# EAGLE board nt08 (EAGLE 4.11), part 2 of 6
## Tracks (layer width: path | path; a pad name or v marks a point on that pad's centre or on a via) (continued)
CK00\  (via drill 0.61) (continued)
  Top 0.254: v323.21,270.51 325.12,268.61 325.12,267.97 IC77.6 | v19.68,473.71 19.05,473.07 19.05,443.87 22.23,440.69 22.23,309.25 v21.59,308.61 | v258.44,307.34 266.7,299.08 v266.7,290.19 | v288.29,286.38 290.19,284.48 v290.19,274.95
  Bottom 0.254: 316.23,269.88 316.23,271.78 317.5,273.05 IC77.12 | 316.23,269.88 322.58,269.88 v323.21,270.51 | v19.68,473.71 -5.71,473.71 -6.99,474.98 M916_3.N2 | v21.59,308.61 22.86,307.34 60.33,307.34 60.96,306.7 104.78,306.7 105.41,307.34 v258.44,307.34 | v266.7,290.19 271.14,285.75 287.65,285.75 v288.29,286.38 | v290.19,274.95 295.27,269.88 316.23,269.88
CK01  (via drill 0.61)
  Top 0.254: IC119.12 517.52,384.18 516.25,384.18 IC119.13 515.62,383.54 514.35,382.27 514.35,340.36 v514.99,339.73 | v317.5,271.14 317.5,270.51 314.96,267.97 IC77.2 | v327.66,334.01 325.75,332.11 325.75,274.95 IC77.9
  Bottom 0.254: IC119.10 522.61,384.18 521.34,382.9 520.07,382.9 518.79,384.18 IC119.12 | v317.5,271.14 318.77,272.42 323.21,272.42 324.49,273.69 IC77.9 | v514.99,339.73 429.26,339.73 423.55,334.01 v327.66,334.01
CK01\  (via drill 0.61)
  Top 0.254: v520.7,268.61 521.97,269.88 521.97,450.85 520.7,452.12 IC121.4 521.34,452.75 522.61,452.75 IC121.5
  Bottom 0.254: v520.7,268.61 471.81,268.61 469.26,271.14 415.29,271.14 412.12,274.32 365.12,274.32 364.49,273.69 328.3,273.69 IC77.8 | IC121.2 516.25,452.75 517.52,451.49 518.79,451.49 520.07,452.75 IC121.4
CLR_DF\  (via drill 0.61)
  Top 0.254: v170.18,464.19 171.45,462.92 v171.45,417.19 | v596.26,427.99 599.44,424.81 599.44,417.83 600.71,416.56 IC137.4
  Bottom 0.254: v170.18,464.19 158.12,464.19 140.97,481.33 50.8,481.33 50.16,480.69 IC15.8 | v171.45,417.19 172.09,417.83 365.12,417.83 375.29,427.99 v596.26,427.99
CLR_DTF\  (via drill 0.61)
  Top 0.254: v567.69,12.7 582.29,27.3 582.29,371.48 589.91,379.1 v589.91,452.75
  Bottom 0.254: v567.69,12.7 523.24,12.7 521.34,14.61 IC112.4 | v589.91,452.75 592.46,455.3 598.8,455.3 600.08,454.02 IC138.4
COMP+SH  (via drill 0.61)
  Top 0.254: v516.89,19.05 516.89,69.85 | 516.89,69.85 518.16,71.12 IC113.3 | 518.16,81.92 516.89,81.92 516.89,69.85 | 518.16,81.92 518.79,81.92 520.07,80.64 IC113.11 | 518.16,81.92 518.16,109.22 IC114.3 518.16,111.76 519.43,113.03 519.43,157.48 518.16,158.75 518.16,176.53 519.43,177.8 519.43,208.28 520.7,209.55 IC116.11
  Bottom 0.254: v516.89,19.05 516.25,19.68 72.39,19.68 72.39,16.51 IC16.1
CSTA  (via drill 0.61)
  Top 0.254: v114.94,516.25 98.42,499.75 v98.42,396.24
  Bottom 0.254: v114.94,516.25 240.66,516.25 241.94,517.52 IC55.10 | v98.42,396.24 93.34,391.16 -2.54,391.16 -3.81,389.89 M916_22.P2
CSTA\  (via drill 0.61)
  Top 0.254: v45.72,236.85 45.72,195.58 IC12.9 | v241.3,425.45 241.3,511.81 240.66,512.45 240.66,516.25 240.03,516.89 IC55.11 | v222.25,419.74 220.98,418.46 220.98,311.15 221.62,310.51 221.62,264.16 219.71,262.25 v219.71,238.76
  Bottom 0.254: v45.72,236.85 82.55,236.85 83.82,238.12 219.71,238.12 | 219.71,238.12 224.79,238.12 226.06,239.4 351.79,239.4 360.68,248.28 404.5,248.28 407.04,250.82 IC87.8 | v241.3,425.45 235.59,419.74 v222.25,419.74 | v219.71,238.76 219.71,238.12
DATA
  Bottom 0.254: IC99.11 440.06,441.32 438.79,440.06 324.49,440.06 323.85,440.69 320.04,436.88 191.13,436.88 189.87,435.61 77.47,435.61 73.03,440.06 71.12,440.06 M916_10.M1
DATA\  (via drill 0.61)
  Top 0.254: v467.36,438.15 471.17,434.34 v471.17,421 467.36,417.19 467.36,191.77 469.26,189.87 v469.26,186.06 | v333.38,38.1 341.63,46.35 341.63,184.15 v341,184.78
  Bottom 0.254: v467.36,438.15 445.77,438.15 443.23,440.69 IC99.10 | v471.17,421 476.25,415.93 512.45,415.93 IC120.1 | v333.38,38.1 325.12,38.1 323.85,36.83 317.5,36.83 315.6,34.92 IC71.2 | v341,184.78 342.26,186.06 v469.26,186.06 471.81,186.06 IC107.1
DB_00\
  Top 0.254: SV10.D -25.4,192.41 -26.67,191.13 -26.67,178.44 -25.4,177.16 SV5.D
  Bottom 0.254: IC24.3 160.66,168.28 156.84,172.09 118.75,172.09 118.11,172.72 22.23,172.72 21.59,172.09 -22.86,172.09 -24.13,173.35 -24.13,175.9 -25.4,175.9 SV5.D
DB_00\_  (via drill 0.61)
  Top 0.254: IC24.1 156.84,167 158.12,167 IC24.2 | v118.11,171.45 118.11,212.09 114.94,215.26 114.94,231.78 115.57,232.41 114.3,233.68 114.3,294.64 116.2,296.55 116.2,341 114.94,342.26 114.94,371.48 116.2,372.75 116.2,434.34 117.47,435.61 117.47,491.49 116.84,492.12 116.84,543.56 113.03,547.37 IC21.1
  Bottom 0.254: v118.11,171.45 121.28,168.28 155.57,168.28 IC24.1
DB_01\  (via drill 0.61)
  Top 0.254: v163.83,172.09 163.83,173.99 IC24.5
  Bottom 0.254: v163.83,172.09 163.19,172.72 119.38,172.72 118.75,173.35 21.59,173.35 20.95,172.72 -18.41,172.72 -19.05,173.35 -19.05,175.9 -20.32,175.9 SV5.J -20.32,177.16 -21.59,177.16 -21.59,191.13 -20.32,192.41 SV10.J
DB_01\_  (via drill 0.61)
  Top 0.254: IC24.7 159.38,174.62 160.66,174.62 IC24.6 | v120.02,426.72 120.02,546.74 120.65,547.37 IC21.4 | v126.36,420.37 139.06,407.67 139.06,287.65 138.43,287.02 138.43,269.88 137.16,268.61 v137.16,177.8
  Bottom 0.254: v126.36,420.37 v120.02,426.72 | v137.16,177.8 137.79,177.16 156.84,177.16 158.12,175.9 IC24.7
DB_02\  (via drill 0.61)
  Top 0.254: v158.75,201.93 161.29,204.47 IC25.3
  Bottom 0.254: v158.75,201.93 157.48,200.66 135.89,200.66 134.62,199.39 57.78,199.39 57.15,200.03 -16.51,200.03 -17.78,201.29 -19.05,201.29 -21.59,198.75 -21.59,194.31 -17.14,194.31 -15.88,193.04 SV10.N -15.24,192.41 -13.97,192.41 -13.97,189.87 -14.61,189.23 -15.24,189.23 -15.24,177.16 SV5.N
DB_02\_  (via drill 0.61)
  Top 0.254: v139.7,207.01 139.7,220.98 138.43,222.25 138.43,268.61 139.06,269.24 139.06,286.38 139.7,287.02 139.7,359.41 146.05,365.76 146.05,445.77 124.46,467.36 124.46,553.72 123.19,554.99 IC21.10
  Bottom 0.254: IC25.2 158.12,205.1 156.84,205.1 IC25.1 156.21,207.01 v139.7,207.01
DB_03\  (via drill 0.61)
  Top 0.254: v134.62,210.19 133.99,209.55 v133.99,202.56 | v-9.53,202.56 -9.53,193.04 SV10.T
  Bottom 0.254: v134.62,210.19 160.66,210.19 163.19,212.72 IC25.5 | v133.99,202.56 v-9.53,202.56 | SV5.T -10.16,177.16 -10.16,189.23 -9.53,189.23 -8.89,189.87 -8.89,192.41 -10.16,192.41 SV10.T
DB_03\_  (via drill 0.61)
  Top 0.254: v148.59,298.45 148.59,361.95 149.86,363.22 149.86,558.16 117.47,558.16 116.2,556.89 IC21.13 | v158.75,292.1 160.02,290.83 160.02,215.9 158.75,214.63 IC25.7
  Bottom 0.254: IC25.7 159.38,212.72 160.66,212.72 IC25.6 | v148.59,298.45 154.94,292.1 v158.75,292.1
DB_04\  (via drill 0.61)
  Top 0.254: v160.02,207.65 160.02,214.63 160.66,215.26 160.66,241.94 161.29,242.57 IC26.3 | v-5.08,206.38 -5.08,193.68 SV10.X
  Bottom 0.254: v160.02,207.65 159.38,208.28 133.99,208.28 131.44,205.74 5.71,205.74 5.08,206.38 v-5.08,206.38 | SV5.X -5.71,176.53 -7.62,178.44 -7.62,189.23 -6.99,189.23 -6.35,189.87 -6.35,193.04 -5.71,193.04 SV10.X
DB_04\_  (via drill 0.61)
  Top 0.254: v148.59,241.94 142.88,236.22 142.88,181.61 149.22,175.26 149.22,19.68 152.4,16.51 IC22.1
  Bottom 0.254: v148.59,241.94 149.86,243.21 155.57,243.21 IC26.1 156.84,243.21 158.12,243.21 IC26.2
DB_05\  (via drill 0.61)
  Top 0.254: v165.1,203.84 165.1,248.92 163.83,250.19 IC26.5 | v0,203.84 0,193.68 SV10.BB | v0,188.59 0,177.16 SV5.BB
  Bottom 0.254: v165.1,203.84 v0,203.84 | v0,188.59 1.27,189.87 1.27,192.41 0,192.41 SV10.BB
DB_05\_  (via drill 0.61)
  Top 0.254: v166.37,243.84 166.37,13.34 161.93,13.34 160.66,14.61 IC22.4 | v162.56,246.38 161.29,247.65 161.29,250.19 IC26.6
  Bottom 0.254: v166.37,243.84 163.83,246.38 v162.56,246.38 | IC26.7 159.38,250.82 160.66,250.82 IC26.6
DB_06\  (via drill 0.61)
  Top 0.254: v149.22,276.23 149.86,275.59 149.86,227.97 144.15,222.25 v144.15,205.74 | v5.08,205.1 5.08,193.68 SV10.FF | v5.08,188.59 5.08,177.16 SV5.FF
  Bottom 0.254: v149.22,276.23 155.57,276.23 160.66,281.31 IC27.3 | v144.15,205.74 143.51,205.1 v5.08,205.1 | v5.08,188.59 6.35,189.87 6.35,192.41 5.08,192.41 SV10.FF
DB_06\_  (via drill 0.61)
  Top 0.254: v163.83,106.68 163.83,90.17 164.47,89.53 164.47,26.04 162.56,24.13 IC22.10 | v140.97,114.94 141.6,115.57 141.6,248.92 140.97,249.56 140.97,254 147.96,260.99 v147.96,280.04
  Bottom 0.254: IC27.2 158.12,281.31 156.84,281.31 IC27.1 155.57,281.31 149.22,281.31 v147.96,280.04 | v163.83,106.68 155.57,114.94 v140.97,114.94
DB_07\  (via drill 0.61)
  Top 0.254: v165.1,257.18 165.1,287.02 163.83,288.29 IC27.5 | v13.97,257.81 10.16,254 10.16,193.68 SV10.LL | v10.16,188.59 10.16,177.16 SV5.LL
  Bottom 0.254: v165.1,257.18 164.47,257.81 v13.97,257.81 | v10.16,188.59 11.43,189.87 11.43,192.41 10.16,192.41 SV10.LL
DB_07\_  (via drill 0.61)
  Top 0.254: v176.53,287.65 174.62,285.75 174.62,198.75 172.09,196.22 172.09,100.97 171.45,100.33 171.45,12.7 157.48,12.7 156.21,13.97 156.21,20.32 154.94,21.59 IC22.13
  Bottom 0.254: v176.53,287.65 163.19,287.65 161.93,288.93 IC27.6 160.66,288.93 159.38,288.93 IC27.7
DB_08\  (via drill 0.61)
  Top 0.254: v158.75,304.8 158.75,316.23 161.29,318.77 IC28.3 | v14.61,303.53 14.61,267.33 15.24,266.7 15.24,197.49 | 15.24,197.49 15.24,193.68 SV10.RR | 15.24,197.49 19.05,193.68 19.05,189.87 16.51,187.32 16.51,178.44 15.24,177.16 SV5.RR
  Bottom 0.254: v158.75,304.8 158.12,304.17 15.24,304.17 v14.61,303.53
DB_08\_  (via drill 0.61)
  Top 0.254: v150.5,223.52 150.5,94.61 152.4,92.71 IC23.1 | v156.21,227.97 157.48,229.24 157.48,317.5 156.21,318.77 IC28.1 156.84,319.4 158.12,319.4 IC28.2
  Bottom 0.254: v150.5,223.52 154.94,227.97 v156.21,227.97
DB_09\  (via drill 0.61)
  Top 0.254: v153.67,199.39 v153.67,325.75 | v-20.32,198.75 -22.86,196.22 -22.86,193.68 SV10.F
  Bottom 0.254: v153.67,325.75 161.93,325.75 163.19,327.02 IC28.5 | v153.67,199.39 152.4,198.12 56.52,198.12 55.88,198.75 v-20.32,198.75 | SV5.F -22.86,177.16 -22.86,189.23 -23.5,189.23 -24.13,189.87 -24.13,193.04 -23.5,193.04 SV10.F
DB_09\_  (via drill 0.61)
  Top 0.254: v167.64,93.98 168.91,95.25 168.91,152.4 167,154.31 167,243.21 167.64,243.84 167.64,272.42 165.74,274.32 165.74,299.08 165.1,299.72 v165.1,325.75 | IC28.7 159.38,327.02 160.66,327.02 IC28.6
  Bottom 0.254: v167.64,93.98 162.56,93.98 160.66,92.08 IC23.4 | v165.1,325.75 165.1,329.56 163.19,329.56 161.93,328.3 IC28.6
DB_10\  (via drill 0.61)
  Top 0.254: v149.86,356.24 150.5,355.6 150.5,227.33 145.41,222.25 v145.41,199.39 | v-17.78,200.03 -17.78,193.68 SV10.L
  Bottom 0.254: v149.86,356.24 159.38,356.24 160.66,357.5 IC29.3 | v145.41,199.39 144.78,198.75 57.15,198.75 56.52,199.39 -17.14,199.39 v-17.78,200.03 | SV5.L -17.78,177.16 -17.78,189.23 -17.14,189.23 -16.51,189.87 -16.51,192.41 -17.78,192.41 SV10.L
DB_10\_  (via drill 0.61)
  Top 0.254: v155.57,149.86 155.57,107.31 162.56,100.33 IC23.10 | v132.72,156.84 132.72,207.01 133.35,207.65 133.35,280.04 135.89,282.57 135.89,356.24 v135.25,356.87
  Bottom 0.254: IC29.2 158.12,357.5 156.84,357.5 IC29.1 155.57,358.14 136.53,358.14 v135.25,356.87 | v155.57,149.86 148.59,156.84 v132.72,156.84
DB_11\  (via drill 0.61)
  Top 0.254: v154.94,201.93 154.31,202.56 154.31,321.94 154.94,322.58 154.94,367.67 156.84,367.67 157.48,367.03 157.48,364.49 158.12,363.86 158.12,362.58 162.56,362.58 163.83,363.86 163.83,364.49 IC29.5 | v-10.79,201.29 -12.7,199.39 -12.7,193.68 SV10.R
  Bottom 0.254: v154.94,201.93 154.31,201.29 135.25,201.29 133.99,200.03 58.42,200.03 57.15,201.29 v-10.79,201.29 | SV5.R -12.7,177.16 -12.7,189.23 -12.06,189.23 -11.43,189.87 -11.43,192.41 -12.7,192.41 SV10.R
DB_11\_  (via drill 0.61)
  Top 0.254: v172.72,96.52 172.72,193.04 175.26,195.58 175.26,285.12 177.8,287.65 177.8,353.06 v174.62,356.24
  Bottom 0.254: v172.72,96.52 157.48,96.52 155.57,98.42 IC23.13 | v174.62,356.24 172.72,358.14 166.37,358.14 160.66,363.86 | 160.66,363.86 159.38,365.12 IC29.7 | 160.66,363.86 161.29,364.49 IC29.6
DF  (via drill 0.61)
  Top 0.254: v30.48,265.43 31.11,266.06 v31.11,411.48 31.11,431.17 v33.02,433.07 | v600.71,417.83 601.98,416.56 v601.98,411.48
  Bottom 0.254: v30.48,265.43 33.02,262.89 IC13.1 | v33.02,433.07 35.56,435.61 43.18,435.61 45.72,438.15 46.99,438.15 48.9,440.06 50.8,440.06 M916_10.E1 | v600.71,417.83 603.25,417.83 605.15,415.93 IC137.6 | v601.98,411.48 601.35,410.85 539.75,410.85 533.4,417.19 517.52,417.19 516.89,416.56 516.89,413.38 451.49,413.38 445.13,419.74 412.12,419.74 403.86,411.48 56.52,411.48 55.88,412.12 42.55,412.12 41.91,411.48 v31.11,411.48
DF\  (via drill 0.61)
  Top 0.254: v228.6,13.34 227.97,13.97 227.97,123.83 227.33,124.46 227.33,182.25 228.6,183.51 228.6,263.52 v227.33,264.8 | v180.34,266.06 180.97,266.7 180.97,318.13 185.42,322.58 185.42,368.3 184.78,368.94 184.78,416.56 | 184.78,416.56 184.78,542.92 192.41,550.54 195.58,550.54 195.58,549.91 IC45.2 | v596.9,429.26 601.98,424.18 601.98,417.83 603.25,416.56 IC137.5 | v520.07,429.26 v517.52,426.72 | v184.15,416.56 184.78,416.56
  Bottom 0.254: v228.6,13.34 234.31,7.62 313.69,7.62 316.87,4.45 IC70.12 | v227.33,264.8 181.61,264.8 v180.34,266.06 | v596.9,429.26 v520.07,429.26 | v517.52,426.72 516.89,427.36 375.92,427.36 365.12,416.56 v184.15,416.56
DTB_00  (via drill 0.61)
  Top 0.254: 444.5,455.93 447.04,458.47 v447.04,476.88 | 444.5,455.93 443.23,454.66 IC100.5 | v430.53,486.41 431.17,487.05 431.17,586.11 432.44,587.38 436.88,587.38 436.88,580.39 438.15,579.12 IC103.3 | v502.29,164.47 502.92,165.1 502.92,237.49 498.48,241.94 v498.48,432.44 | v447.04,436.88 444.5,439.42 444.5,455.93 | v83.19,415.29 76.83,408.94 76.83,365.12 77.47,364.49 M916_9.A2 | v375.92,438.79 v375.92,426.08
  Bottom 0.254: v447.04,476.88 437.51,486.41 v430.53,486.41 | v502.29,164.47 522.61,164.47 527.68,159.38 542.29,159.38 543.56,160.66 591.18,160.66 592.46,159.38 IC129.1 | v498.48,432.44 494.03,436.88 v447.04,436.88 445.77,436.88 443.23,439.42 376.56,439.42 v375.92,438.79 | v83.19,415.29 365.12,415.29 v375.92,426.08
DTB_00\  (via drill 0.61)
  Top 0.254: v427.36,457.2 427.99,457.83 427.99,531.5 363.22,596.26 114.3,596.26 114.3,551.18 115.57,549.91 IC21.2
  Bottom 0.254: v427.36,457.2 445.77,457.2 445.77,454.66 IC100.6
DTB_01  (via drill 0.61)
  Top 0.254: v488.95,167.64 488.95,121.92 486.41,119.38 486.41,62.23 477.52,53.34 IC105.12 | v486.41,454.66 498.48,442.6 498.48,437.51 497.2,436.25 497.2,196.85 501.65,192.41 v501.65,173.99 | v104.14,384.18 111.12,391.16 111.12,439.42 113.03,441.32 114.3,441.32 v114.3,438.79
  Bottom 0.254: v488.95,167.64 495.3,173.99 v501.65,173.99 532.76,173.99 554.36,195.58 593.09,195.58 IC130.1 | IC100.9 445.13,461.64 443.87,462.92 442.6,462.92 441.96,462.28 441.96,457.83 447.04,457.83 450.21,454.66 v486.41,454.66 486.41,452.12 474.35,440.06 445.13,440.06 444.5,440.69 444.5,443.23 443.87,443.87 432.44,443.87 431.17,442.6 323.21,442.6 319.4,438.79 190.5,438.79 188.59,436.88 116.2,436.88 v114.3,438.79 | v104.14,384.18 102.23,384.18 83.82,365.76 81.92,365.76 81.92,361.31 M916_9.B2
DTB_01\  (via drill 0.61)
  Top 0.254: v425.45,464.82 425.45,518.79 v400.05,544.2
  Bottom 0.254: v425.45,464.82 444.5,464.82 447.68,461.64 IC100.8 | v400.05,544.2 149.22,544.2 148.59,543.56 128.27,543.56 123.83,548 IC21.5
DTB_02  (via drill 0.61)
  Top 0.254: v494.03,218.44 494.03,3.17 478.15,3.17 478.15,4.45 477.52,5.08 IC104.3 | v443.23,486.41 443.23,490.22 IC101.5 | v502.92,476.88 506.1,473.71 v506.1,330.2 v506.1,231.78 | v85.09,347.35 85.09,363.86 M916_9.C2 | v425.45,337.19 429.89,332.74 v429.89,330.83
  Bottom 0.254: 506.73,231.14 508.63,233.04 593.73,233.04 595,234.31 IC131.2 | 506.73,231.14 v494.03,218.44 | v443.23,486.41 452.75,476.88 v502.92,476.88 | v506.1,231.78 506.73,231.14 | v85.09,347.35 89.53,342.9 185.42,342.9 187.32,344.81 349.25,344.81 356.87,337.19 v425.45,337.19 | v429.89,330.83 432.44,328.3 469.26,328.3 471.17,330.2 v506.1,330.2
DTB_02\  (via drill 0.61)
  Top 0.254: v414.65,492.12 v417.19,494.67 | v147.32,487.05 129.54,504.82 129.54,553.72 128.27,554.99 IC21.8
  Bottom 0.254: v417.19,494.67 445.77,494.67 445.77,492.76 IC101.6 | v414.65,492.12 409.57,487.05 v147.32,487.05
DTB_03  (via drill 0.61)
  Top 0.254: v443.23,455.93 444.5,457.2 444.5,487.68 447.04,490.22 447.04,496.57 445.77,497.84 IC101.9 | v114.3,378.46 114.94,379.1 114.94,438.15 115.57,438.79 115.57,490.86 v114.94,491.49
  Bottom 0.254: v443.23,455.93 438.15,455.93 436.25,454.02 IC100.2 | v114.3,378.46 102.87,378.46 89.53,365.12 88.27,365.12 88.27,361.31 M916_9.D2 | v114.94,491.49 116.2,492.76 198.75,492.76 203.2,488.31 341,488.31 354.33,501.65 443.23,501.65 445.13,499.75 IC101.9
DTB_03\  (via drill 0.61)
  Top 0.254: v433.07,558.8 444.5,547.37 v444.5,502.29
  Bottom 0.254: v433.07,558.8 123.19,558.8 121.28,556.89 IC21.11 | v444.5,502.29 445.77,501.01 446.4,501.01 447.68,499.75 IC101.8
DTB_04  (via drill 0.61)
  Top 0.254: v440.69,463.55 441.96,464.82 441.96,527.05 443.23,528.32 IC102.5 | v90.81,437.51 90.81,416.56 92.08,415.29 92.08,365.12 91.44,364.49 M916_9.E2 | v320.04,438.15 323.85,441.96 v323.85,456.56
  Bottom 0.254: v440.69,463.55 438.79,461.64 IC100.12 437.51,460.38 436.25,459.11 422.91,459.11 421.64,457.83 325.12,457.83 v323.85,456.56 | v90.81,437.51 92.08,438.79 113.03,438.79 115.57,436.25 189.23,436.25 191.13,438.15 v320.04,438.15
DTB_04\  (via drill 0.61)
  Top 0.254: v118.11,514.99 118.11,434.98 117.47,434.34 117.47,281.31 118.75,280.04 118.75,270.51 118.11,269.88 118.11,219.07 120.65,216.53 120.65,13.34 153.03,13.34 154.31,14.61 IC22.2 | v445.77,514.99 445.77,528.32 IC102.6
  Bottom 0.254: v118.11,514.99 118.75,515.62 225.43,515.62 227.33,513.72 243.21,513.72 244.47,514.99 v445.77,514.99
DTB_05  (via drill 0.61)
  Top 0.254: v444.5,493.39 444.5,501.01 447.04,503.56 447.04,534.67 445.77,535.94 IC102.9 | v111.12,362.58 111.76,363.22 111.76,374.65 115.57,378.46 115.57,437.51 116.2,438.15 v116.2,491.49
  Bottom 0.254: 437.51,493.39 436.25,492.12 IC101.2 | 437.51,493.39 v444.5,493.39 | v111.12,362.58 95.89,362.58 94.61,361.31 M916_9.F2 | v116.2,491.49 119.38,488.31 201.93,488.31 202.56,487.68 344.81,487.68 349.25,492.12 390.52,492.12 391.8,493.39 437.51,493.39
DTB_05\  (via drill 0.61)
  Top 0.254: v446.4,10.79 459.74,24.13 v459.74,137.16 | v455.93,140.97 455.3,141.6 455.3,337.82 454.02,339.09 v454.02,531.5
  Bottom 0.254: v446.4,10.79 429.26,-6.35 247.01,-6.35 229.24,11.43 166.37,11.43 163.19,14.61 IC22.5 | v455.93,140.97 v459.74,137.16 | v454.02,531.5 448.94,536.58 IC102.8
DTB_06  (via drill 0.61)
  Top 0.254: v93.34,245.11 93.98,245.75 93.98,282.57 95.25,283.85 v95.25,344.81 95.25,362.58 96.52,363.86 M916_9.H2 | v410.21,497.2 410.85,496.57 410.85,413.38 411.48,412.75 411.48,376.56 406.4,371.48 v406.4,347.98
  Bottom 0.254: v93.34,245.11 97.79,240.66 164.47,240.66 168.28,244.47 198.75,244.47 201.29,241.94 281.31,241.94 282.57,243.21 IC62.5 | v410.21,497.2 436.25,497.2 437.51,498.48 IC101.12 | v406.4,347.98 405.76,348.62 326.39,348.62 323.85,346.07 288.93,346.07 287.02,347.98 229.87,347.98 227.97,346.07 186.06,346.07 184.78,344.81 v95.25,344.81
DTB_06\  (via drill 0.61)
  Top 0.254: v168.91,241.3 168.91,180.97 169.54,180.34 169.54,26.04 167.64,24.13 IC22.8
  Bottom 0.254: v168.91,241.3 171.45,243.84 198.12,243.84 200.66,241.3 283.21,241.3 285.12,243.21 IC62.6
DTB_07  (via drill 0.61)
  Top 0.254: v280.67,351.15 280.67,334.01 285.75,328.93 IC64.9 | v100.97,351.15 100.97,360.68 M916_9.J2 | v426.72,526.41 426.72,457.83 423.55,454.66 423.55,378.46 425.45,376.56 v425.45,351.79
  Bottom 0.254: v100.97,351.15 104.78,351.15 106.05,352.43 279.4,352.43 v280.67,351.15 424.81,351.15 v425.45,351.79 | v426.72,526.41 432.44,526.41 434.98,528.96 IC102.2
DTB_07\  (via drill 0.61)
  Top 0.254: v163.19,30.48 163.19,27.3 160.02,24.13 IC22.11 | v173.99,41.27 174.62,41.91 174.62,106.05 173.99,106.68 173.99,115.57 177.16,118.75 177.16,256.54 v179.07,258.44 | v295.91,266.7 294.64,267.97 294.64,302.89 292.74,304.8 v292.74,327.02
  Bottom 0.254: v173.99,41.27 v163.19,30.48 | v179.07,258.44 179.71,259.08 242.57,259.08 249.56,266.06 267.97,266.06 269.24,267.33 295.27,267.33 v295.91,266.7 | v292.74,327.02 288.93,327.02 IC64.8
DTB_08  (via drill 0.61)
  Top 0.254: v284.48,306.07 284.48,288.29 283.85,287.65 283.85,283.85 283.21,283.21 IC63.5 | v270.51,307.34 269.24,308.61 v269.24,351.15 269.24,396.88 267.33,398.78 v267.33,539.12 | v104.78,349.88 103.5,351.15 103.5,363.86 M916_9.K2
  Bottom 0.254: v284.48,306.07 283.21,307.34 v270.51,307.34 | v269.24,351.15 268.61,351.79 106.68,351.79 v104.78,349.88 | v267.33,539.12 436.25,539.12 437.51,537.85 IC102.12
DTB_08\  (via drill 0.61)
  Top 0.254: v147.96,93.98 142.24,99.69 v142.24,249.56 | v266.7,252.09 268.61,254 v268.61,254.63 | v285.75,255.27 285.75,280.67 IC63.6
  Bottom 0.254: v147.96,93.98 152.4,93.98 154.31,92.08 IC23.2 | v142.24,249.56 164.47,249.56 167.64,252.73 266.06,252.73 v266.7,252.09 | v268.61,254.63 269.24,255.27 v285.75,255.27
DTB_09  (via drill 0.61)
  Top 0.254: v284.48,245.75 284.48,287.02 285.75,288.29 IC63.9 | v106.68,346.71 106.68,360.68 M916_9.L2 | v289.56,287.65 v289.56,347.98
  Bottom 0.254: v284.48,245.75 277.5,245.75 276.23,244.47 IC62.2 | v106.68,346.71 107.31,347.35 226.69,347.35 228.6,349.25 288.29,349.25 v289.56,347.98 | v289.56,287.65 287.65,287.65 286.38,288.93 IC63.9
DTB_09\  (via drill 0.61)
  Top 0.254: v163.19,87.63 163.19,89.53 162.56,90.17 IC23.5 | v301.62,87 302.26,87.63 302.26,255.27 304.8,257.81 v304.8,286.38
  Bottom 0.254: v163.19,87.63 163.83,87 v301.62,87 | v304.8,286.38 302.26,288.93 288.93,288.93 IC63.8
DTB_10  (via drill 0.61)
  Top 0.254: 278.13,329.56 281.31,329.56 281.94,328.93 281.94,322.58 283.21,321.31 IC64.5 | 278.13,329.56 278.13,328.93 IC64.12 | v109.86,354.96 109.86,363.86 M916_9.M2 | 278.13,329.56 v278.13,354.96
  Bottom 0.254: v278.13,354.96 v109.86,354.96
DTB_10\  (via drill 0.61)
  Top 0.254: v170.81,100.97 170.18,101.6 170.18,180.97 169.54,181.61 169.54,194.94 173.99,199.39 173.99,286.38 v176.53,288.93 | v285.75,293.37 285.75,318.77 IC64.6
  Bottom 0.254: v170.81,100.97 169.54,100.97 168.28,99.69 IC23.8 | v176.53,288.93 183.51,295.91 237.49,295.91 240.03,293.37 282.57,293.37 283.21,294 285.12,294 v285.75,293.37
DTB_11  (via drill 0.61)
  Top 0.254: v287.02,269.88 287.02,254 285.75,252.73 IC62.9 | v275.59,271.14 v275.59,274.95 275.59,280.67 IC63.2 | v140.97,359.41 141.6,358.77 141.6,275.59 v140.97,274.95
  Bottom 0.254: v287.02,269.88 285.75,271.14 v275.59,271.14 | v140.97,359.41 140.34,358.77 115.57,358.77 113.67,360.68 M916_9.N2 | v140.97,274.95 141.6,274.32 243.21,274.32 244.47,275.59 274.95,275.59 v275.59,274.95
DTB_11\  (via drill 0.61)
  Top 0.254: v297.81,106.05 299.72,107.95 299.72,168.28 300.99,169.54 v300.99,249.56
  Bottom 0.254: v297.81,106.05 219.71,106.05 215.26,101.6 200.66,101.6 200.03,102.23 163.19,102.23 160.66,99.69 IC23.11 | v300.99,249.56 299.72,250.82 288.93,250.82 IC62.8
DTF  (via drill 0.61)
  Top 0.254: v35.56,446.4 35.56,499.11 36.83,500.38 IC6.2 | v31.75,24.77 29.84,26.67 29.84,153.03 26.04,156.84 26.04,189.23 24.77,190.5 v24.77,227.97 | v19.68,233.04 19.05,233.68 v19.05,430.53 | v61.59,485.77 v67.31,480.06
  Bottom 0.254: M916_10.C1 44.45,440.69 41.27,440.69 v35.56,446.4 34.92,446.4 v19.05,430.53 | v31.75,24.77 32.38,25.4 72.39,25.4 74.3,23.5 IC16.13 | v19.68,233.04 v24.77,227.97 | v67.31,480.06 111.76,480.06 128.91,462.92 329.56,462.92 335.92,469.26 422.27,469.26 426.08,465.45 526.41,465.45 532.76,459.11 600.08,459.11 605.15,454.02 IC138.6 | v61.59,485.77 47.62,499.75 38.73,499.75 37.47,501.01 IC6.2
DTF\  (via drill 0.61)
  Top 0.254: v259.71,6.35 249.56,16.51 v249.56,133.35 | v196.22,142.88 196.85,143.51 196.85,290.83 197.49,291.46 198.12,291.46 | 198.12,291.46 200.66,291.46 200.66,290.83 IC39.11 | v589.91,455.93 582.29,448.31 v582.29,373.38 | v199.39,361.95 198.12,360.68 198.12,291.46
  Bottom 0.254: v259.71,6.35 267.33,-1.27 288.29,-1.27 292.74,-5.71 318.13,-5.71 319.4,-4.45 IC70.4 | v249.56,133.35 240.03,142.88 v196.22,142.88 | v589.91,455.93 600.71,455.93 602.62,454.02 IC138.5 | v582.29,373.38 570.23,361.31 353.69,361.31 351.15,363.86 329.56,363.86 328.93,363.22 200.66,363.22 v199.39,361.95
DTSF  (via drill 0.61)
  Top 0.254: v85.09,81.28 85.09,87.63 82.55,90.17 IC17.5 | v342.9,88.9 342.26,89.53 342.26,226.69 341.63,227.33 341.63,314.32 341,314.96 341,350.52 346.71,356.24 v346.71,488.31
  Bottom 0.254: v85.09,81.28 87,79.38 309.25,79.38 316.23,86.36 340.36,86.36 v342.9,88.9 | v346.71,488.31 349.25,490.86 390.52,490.86 391.8,489.58 393.06,489.58 394.33,490.86 IC91.2
DTSF\
  Top 0.254: IC88.8 407.67,383.54 407.67,381 408.94,379.73 410.85,379.73 410.85,412.12 410.21,412.75 410.21,494.03 392.43,494.03 392.43,492.76 IC91.1
EA_00\  (via drill 0.61)
  Top 0.254: v17.78,180.97 17.78,177.16 SV5.TT
  Bottom 0.254: IC50.3 240.66,186.06 238.76,184.15 229.87,184.15 229.24,184.78 149.86,184.78 144.78,179.71 137.79,179.71 136.53,180.97 56.52,180.97 53.34,177.8 19.68,177.8 18.41,176.53 SV5.TT | v17.78,180.97 16.51,180.97 16.51,191.13 17.78,192.41 SV10.TT
EA_00\_  (via drill 0.61)
  Top 0.254: v230.5,167 230.5,18.41 232.41,16.51 IC46.1 | v236.22,172.09 236.22,185.42 IC50.1
  Bottom 0.254: v230.5,167 235.59,172.09 v236.22,172.09 | IC50.2 238.12,186.06 236.85,186.06 IC50.1
EA_01\  (via drill 0.61)
  Top 0.254: v147.32,189.87 144.78,187.32 v144.78,180.97 | v13.97,180.97 12.7,179.71 12.7,177.16 SV5.NN
  Bottom 0.254: v147.32,189.87 239.4,189.87 243.21,193.68 IC50.5 | v144.78,180.97 144.15,181.61 55.88,181.61 52.7,178.44 15.24,178.44 13.34,176.53 SV5.NN | v13.97,180.97 13.97,191.13 12.7,192.41 SV10.NN
EA_01\_  (via drill 0.61)
  Top 0.254: v247.01,167.64 247.01,125.73 248.92,123.83 248.92,13.34 241.94,13.34 240.66,14.61 IC46.4 | v242.57,172.09 240.03,174.62 240.03,190.5 238.76,191.77 238.76,193.04 IC50.7
  Bottom 0.254: v247.01,167.64 v242.57,172.09 | IC50.6 240.66,193.68 239.4,193.68 IC50.7
EA_02\  (via drill 0.61)
  Top 0.254: v242.57,173.35 242.57,189.23 240.03,191.77 240.03,222.25 241.3,223.52 IC51.3 | v8.89,180.97 7.62,179.71 7.62,177.16 SV5.JJ
  Bottom 0.254: v242.57,173.35 131.44,173.35 129.54,175.26 9.53,175.26 8.26,176.53 SV5.JJ | v8.89,180.97 8.89,191.13 7.62,192.41 SV10.JJ
EA_02\_  (via drill 0.61)
  Top 0.254: v247.65,221.62 247.65,188.59 245.75,186.69 245.75,167.64 246.38,167 246.38,27.94 242.57,24.13 IC46.10
  Bottom 0.254: IC51.1 236.85,224.16 238.12,224.16 IC51.2 239.4,224.16 240.66,222.88 246.38,222.88 v247.65,221.62
EF  (via drill 0.61)
  Top 0.254: v40.64,354.33 40.64,270.51 IC13.11 | v73.66,57.78 73.66,27.94 77.47,24.13 IC16.12 | v46.99,71.12 44.45,73.66 44.45,257.81 46.99,260.35 46.99,270.51 43.18,274.32 43.18,356.87 IC14.5 | v111.12,356.24 111.12,361.31 112.39,362.58 112.39,367.03 M916_9.N1
  Bottom 0.254: 42.55,356.24 43.18,356.87 IC14.5 | 42.55,356.24 v40.64,354.33 | v73.66,57.78 60.33,71.12 v46.99,71.12 | 42.55,356.24 v111.12,356.24
EF\  (via drill 0.61)
  Top 0.254: v69.85,359.41 76.2,365.76 76.2,418.46 81.92,424.18 v81.92,543.56 | v167,553.09 167.64,553.72 167.64,554.99 IC32.8
  Bottom 0.254: v69.85,359.41 69.22,360.05 47.62,360.05 46.35,358.77 IC14.6 | v81.92,543.56 83.19,544.83 102.23,544.83 110.49,553.09 v167,553.09
END  (via drill 0.61)
  Top 0.254: v12.06,412.75 v12.06,431.17 | v119.38,400.05 119.38,367.67 M916_9.R1
  Bottom 0.254: v12.06,431.17 2.54,440.69 IC5.5 | v12.06,412.75 24.77,400.05 v119.38,400.05
END\  (via drill 0.61)
  Top 0.254: v57.15,51.44 60.96,55.24 v60.96,156.84 | v195.58,163.19 195.58,204.47 IC38.2 | v20.32,443.87 22.86,441.32 22.86,172.09 22.23,171.45 v22.23,58.42
  Bottom 0.254: 42.55,51.44 41.27,52.7 IC10.4 | 42.55,51.44 v57.15,51.44 | v60.96,156.84 67.31,163.19 v195.58,163.19 | v20.32,443.87 6.99,443.87 5.71,442.6 IC5.6 | v22.23,58.42 29.21,51.44 42.55,51.44
ENI  (via drill 0.61)
  Top 0.254: 102.23,300.99 102.23,301.62 104.14,303.53 104.14,347.98 106.05,349.88 106.05,359.41 105.41,360.05 105.41,366.39 106.05,367.03 M916_9.L1 | 102.23,300.99 102.23,290.83 97.79,286.38 97.79,254 95.89,252.09 95.89,132.08 93.98,130.18 93.98,66.67 86.36,59.05 86.36,13.34 81.92,13.34 80.64,14.61 IC16.4 | v438.15,293.37 438.15,290.83 IC95.12 | v260.99,296.55 v257.18,300.36 | v102.87,300.99 102.23,300.99
  Bottom 0.254: v438.15,293.37 433.7,297.81 263.52,297.81 262.25,296.55 v260.99,296.55 | v257.18,300.36 256.54,300.99 v102.87,300.99
ENI\  (via drill 0.61)
  Top 0.254: v162.56,537.85 162.56,547.37 IC32.5 | v429.26,518.16 428.62,517.52 428.62,352.43 431.8,349.25 431.8,296.55 435.61,292.74 435.61,290.83 IC95.13
  Bottom 0.254: v162.56,537.85 176.53,523.88 273.69,523.88 276.23,521.34 285.75,521.34 288.93,518.16 v429.26,518.16
FR_00  (via drill 0.61)
  Top 0.254: v321.31,1.91 321.31,39.37 322.58,40.64 IC71.10 | v478.79,365.12 478.79,374.65 480.06,375.92 IC110.4 | v137.16,373.38 v134.62,370.84 | v362.58,44.45 374.01,55.88 374.01,150.5 370.2,154.31 370.2,339.09 368.3,341 v368.3,368.94
  Bottom 0.254: v321.31,1.91 280.04,1.91 278.76,3.17 IC58.12 | v478.79,365.12 477.52,363.86 384.18,363.86 378.46,369.57 368.3,369.57 | 368.3,369.57 316.23,369.57 313.69,372.11 264.16,372.11 263.52,372.75 262.25,371.48 161.93,371.48 160.02,373.38 v137.16,373.38 | v134.62,370.84 132.72,368.94 95.89,368.94 94.61,367.67 M916_9.F1 | v362.58,44.45 325.12,44.45 323.21,42.55 IC71.10 | 368.3,369.57 v368.3,368.94
FR_00\  (via drill 0.61)
  Top 0.254: v330.83,0.64 354.33,24.13 354.33,53.98 358.77,58.42 358.77,60.96 358.14,61.59 358.14,203.2 v361.95,207.01 | v485.14,232.41 486.41,233.68 486.41,266.06 485.14,267.33 485.14,269.24 IC108.9 485.14,271.78 485.14,316.87 v486.41,318.13 | v293.37,471.81 295.27,469.9 295.27,323.21 v295.91,322.58
  Bottom 0.254: v330.83,0.64 278.76,0.64 276.23,3.17 IC58.13 | v361.95,207.01 368.3,213.36 466.09,213.36 v485.14,232.41 | v486.41,318.13 474.35,318.13 473.07,319.4 IC109.1 471.81,320.68 470.54,321.94 296.55,321.94 v295.91,322.58 | v293.37,471.81 278.76,471.81 275.59,474.98 166.37,474.98 166.37,471.17 165.74,470.54 164.47,470.54 163.19,471.81 IC31.5
FR_01  (via drill 0.61)
  Top 0.254: v285.75,27.3 285.75,5.08 IC58.9 | v40.64,41.91 39.37,43.18 39.37,114.3 38.1,115.57 38.1,116.84 IC11.12 | 213.36,356.87 211.46,358.77 v211.46,374.01 | v214,356.24 213.36,356.87 | v542.92,432.44 v542.92,305.44 v542.92,221.62 | v551.18,478.79 551.18,438.15 IC124.22 | v322.58,306.7 322.58,356.87 IC78.5 | v214.63,38.73 214.63,203.84 215.26,204.47 215.26,246.38 213.36,248.28 213.36,356.87
  Bottom 0.254: 214.63,27.3 196.22,27.3 180.97,42.55 57.78,42.55 57.15,41.91 v40.64,41.91 | 214.63,27.3 v285.75,27.3 | v214,356.24 320.68,356.24 321.94,357.5 IC78.5 | v211.46,374.01 210.82,374.65 101.6,374.65 97.79,370.84 M916_9.H1 | v542.92,221.62 529.59,208.28 527.05,208.28 527.05,201.93 526.41,201.29 522.61,201.29 521.34,202.56 IC116.4 | v542.92,432.44 545.47,434.98 549.27,434.98 550.54,436.25 IC124.22 | v551.18,478.79 573.4,501.01 593.73,501.01 595,499.75 IC139.13 | v322.58,306.7 323.85,305.44 481.33,305.44 481.96,306.07 492.12,306.07 492.76,305.44 v542.92,305.44 | v214.63,38.73 214.63,27.3
FR_01\  (via drill 0.61)
  Top 0.254: v287.02,21.59 287.02,6.35 288.29,5.08 IC58.8 | v198.12,478.15 200.66,475.62 v200.66,313.06 | v184.78,310.51 184.78,194.94 183.51,193.68 183.51,175.9 187.32,172.09 187.32,114.94 187.96,114.3 v187.96,21.59
  Bottom 0.254: 187.96,20.95 238.12,20.95 | 187.96,20.95 87,20.95 85.72,22.23 IC16.9 | 238.12,20.95 239.4,22.23 IC46.11 | v287.02,21.59 286.38,20.95 238.12,20.95 | v198.12,478.15 169.54,478.15 168.28,479.43 IC31.8 | v200.66,313.06 198.12,310.51 v184.78,310.51 | v187.96,21.59 187.96,20.95
FR_02  (via drill 0.61)
  Top 0.254: v438.15,255.27 438.15,252.73 IC94.12 | v551.82,255.27 553.72,257.18 553.72,419.1 552.45,420.37 552.45,425.45 553.72,426.72 553.72,435.61 IC124.21 | v102.87,347.35 99.06,351.15 99.06,366.39 99.69,367.03 M916_9.J1 | v407.67,342.26 v407.67,255.27
  Bottom 0.254: v551.82,255.27 v438.15,255.27 v407.67,255.27 | v102.87,347.35 104.78,345.44 184.15,345.44 185.42,346.71 227.33,346.71 229.24,348.62 287.65,348.62 289.56,346.71 323.21,346.71 325.75,349.25 410.21,349.25 411.48,347.98 411.48,342.26 v407.67,342.26
FR_02\  (via drill 0.61)
  Top 0.254: v162.56,485.77 162.56,483.87 160.02,481.33 IC31.11 | v414.65,486.41 415.93,485.14 415.93,446.4 417.19,445.13 417.19,325.12 415.29,323.21 v415.29,273.69 | v435.61,272.42 435.61,252.73 IC94.13
  Bottom 0.254: v162.56,485.77 163.19,486.41 v414.65,486.41 | v415.29,273.69 416.56,272.42 v435.61,272.42
FR_03  (via drill 0.61)
  Top 0.254: v313.69,354.96 313.69,363.22 314.96,364.49 IC78.13 | v104.78,353.69 104.78,369.57 104.14,370.2 M916_9.K1 | v397.51,356.24 v397.51,255.27 | v493.39,431.17 486.41,424.18 v486.41,358.14
  Bottom 0.254: v104.78,353.69 312.42,353.69 v313.69,354.96 320.68,354.96 321.94,356.24 v397.51,356.24 484.5,356.24 v486.41,358.14 | v397.51,255.27 398.78,254 401.32,254 401.95,253.37 443.87,253.37 445.13,252.09 IC94.9 | v493.39,431.17 550.54,431.17 555.62,436.25 IC124.20
FR_03\  (via drill 0.61)
  Top 0.254: v274.32,158.12 274.32,113.03 275.59,111.76 IC60.2 | v445.77,163.83 447.04,165.1 447.04,248.92 448.31,250.19 IC94.8 | v172.09,550.54 173.35,549.27 173.35,363.86 179.07,358.14 179.07,264.8 180.97,262.89 180.97,194.94 179.71,193.68 v179.71,175.9
  Bottom 0.254: v445.77,163.83 431.8,163.83 430.53,165.1 394.33,165.1 393.06,163.83 280.04,163.83 v274.32,158.12 257.81,174.62 180.97,174.62 v179.71,175.9 | v172.09,550.54 156.84,550.54 155.57,549.27 IC32.2
FR_03_  (via drill 0.61)
  Top 0.254: v493.39,429.26 487.68,423.55 487.68,386.08 IC110.8 | IC124.18 560.71,436.25 559.43,436.25 IC124.19
  Bottom 0.254: v493.39,429.26 494.67,430.53 552.45,430.53 558.16,436.25 IC124.19
GND  (via drill 0.61)
  Top 0.254: IC7.7 7.62,541.02 8.89,542.29 8.89,575.31 7.62,576.58 IC8.7 | M916_2.T1 87,424.81 88.27,426.08 88.27,433.07 88.9,433.7 M916_10.U2 89.53,434.34 89.53,438.79 90.81,438.79 92.08,437.51 M916_10.V1 | 46.35,417.83 45.72,418.46 45.72,421 M916_2.C2 | 46.35,417.83 49.53,414.65 49.53,360.68 48.26,359.41 IC14.7 | 46.35,417.83 46.35,429.26 47.62,430.53 M916_10.D2 48.9,431.17 49.53,431.8 49.53,471.17 IC15.7 49.53,473.71 50.8,474.98 50.8,499.11 49.53,500.38 IC6.7 49.53,502.92 45.72,506.73 45.72,510.54 46.35,511.18 46.35,572.77 45.72,573.4 M916_4.C2 | v243.84,89.53 243.84,109.22 IC48.4 | IC37.4 204.47,128.27 205.74,127 205.74,93.98 204.47,92.71 IC36.4 | IC46.3 237.49,16.51 237.49,21.59 IC46.12 237.49,24.13 237.49,90.17 IC47.3 | IC46.7 247.01,14.61 245.75,14.61 IC46.6 245.11,16.51 245.11,21.59 IC46.9 | v275.59,14.61 275.59,10.16 280.67,5.08 IC58.11 | IC35.4 204.47,52.07 205.1,51.44 205.1,24.77 205.74,24.13 205.74,19.68 204.47,18.41 204.47,16.51 IC34.4 | M916_23.C2 -36.83,466.09 -37.47,466.73 -37.47,477.52 -36.83,478.15 M916_3.C2 | 6.35,420.37 6.35,419.1 7.62,417.83 IC4.7 | 6.35,420.37 6.35,439.42 7.62,440.69 IC5.7 | IC4.5 3.17,415.93 3.17,394.33 4.45,393.06 M916_22.T1 5.71,392.43 6.35,391.8 6.35,335.28 7.62,334.01 IC3.7 7.62,331.47 5.71,329.56 5.71,316.87 M916_21.T1 5.71,316.23 5.71,313.69 8.89,310.51 8.89,294.64 7.62,293.37 IC2.7 6.99,292.74 5.71,294 3.81,294 3.81,267.97 5.08,266.7 5.08,240.66 M916_20.T1 5.71,240.03 6.35,239.4 6.35,228.6 5.71,227.97 M916_19.T1 4.45,227.33 3.17,226.06 3.17,207.65 1.27,205.74 1.27,190.5 | 6.35,420.37 3.81,422.91 3.81,468 4.45,468.63 M916_23.T1
  Top 0.254: SV2.A -27.3,55.88 -26.04,55.88 SV2.C -24.77,55.88 -23.5,55.88 SV2.E -22.23,55.88 -20.95,55.88 SV2.H -19.68,55.88 -18.41,55.88 SV2.K -17.14,55.88 -15.88,55.88 SV2.M -14.61,55.88 -13.34,55.88 SV2.P | SV2.B -27.94,57.78 -27.94,56.52 SV2.A | SV2.S -9.53,55.88 -8.26,55.88 SV2.U -6.99,55.88 -5.71,55.88 SV2.W -4.45,55.88 -3.17,55.88 SV2.Y -1.91,55.88 -0.64,55.88 SV2.AA 0.64,55.88 1.91,55.88 SV2.CC 3.17,55.88 4.45,55.88 SV2.EE 5.71,55.88 6.99,55.88 SV2.HH 8.26,55.88 9.53,55.88 SV2.KK 10.79,55.88 12.06,55.88 SV2.MM 13.34,55.88 14.61,55.88 SV2.PP 15.88,55.88 17.14,55.88 SV2.SS 18.41,55.88 19.68,55.88 SV2.UU 20.32,56.52 20.32,57.78 SV2.VV 20.32,59.05 20.32,70.48 SV7.UU | SV7.B -27.94,73.03 -27.94,71.75 SV7.A | SV7.E -23.5,71.12 -24.77,71.12 SV7.C | SV7.H -19.68,71.12 -18.41,71.12 SV7.K -17.14,71.12 -15.88,71.12 SV7.M -14.61,71.12 -13.34,71.12 SV7.P | SV7.S -9.53,71.12 -8.26,71.12 SV7.U -6.99,71.12 -5.71,71.12 SV7.W -4.45,71.12 -3.17,71.12 SV7.Y -1.91,71.12 -0.64,71.12 SV7.AA 0.64,71.12 1.91,71.12 SV7.CC 3.17,71.12 4.45,71.12 SV7.EE 5.71,71.12 6.99,71.12 SV7.HH 8.26,71.12 9.53,71.12 SV7.KK 10.79,71.12 12.06,71.12 SV7.MM | SV7.UU 19.68,71.12 18.41,71.12 SV7.SS | SV7.UU 20.32,71.75 20.32,73.03 SV7.VV 20.32,74.3 20.32,98.42 SV3.UU 20.32,99.69 20.32,100.97 SV3.VV 20.32,102.23 20.32,118.75 SV8.UU 20.32,120.02 20.32,121.28 SV8.VV 20.32,122.56 20.32,136.53 SV4.UU 20.32,137.79 20.32,139.06 SV4.VV 20.32,140.34 20.32,151.76 SV9.UU | SV6.A -27.94,38.73 -27.94,40.01 SV6.B -27.94,41.27 -27.94,55.24 SV2.A | SV6.E -22.23,38.1 -20.95,38.1 SV6.H -19.68,38.1 -18.41,38.1 SV6.K -17.14,38.1 -15.88,38.1 SV6.M -14.61,38.1 -13.34,38.1 SV6.P -12.06,38.1 -10.79,38.1 SV6.S -9.53,38.1 -8.26,38.1 SV6.U -6.99,38.1 -5.71,38.1 SV6.W -4.45,38.1 -3.17,38.1 SV6.Y
  Top 0.254: SV6.AA 0.64,38.1 1.91,38.1 SV6.CC 3.17,38.1 4.45,38.1 SV6.EE 5.71,38.1 6.99,38.1 SV6.HH 8.26,38.1 9.53,38.1 SV6.KK | SV6.VV 20.32,40.01 20.32,38.73 SV6.UU 20.32,37.47 20.32,23.5 SV1.VV 20.32,22.23 20.32,20.95 SV1.UU 19.68,20.32 18.41,20.32 SV1.SS 17.14,20.32 15.88,20.32 SV1.PP 14.61,20.32 13.34,20.32 SV1.MM 12.06,20.32 10.79,20.32 SV1.KK 9.53,20.32 8.26,20.32 SV1.HH 6.99,20.32 5.71,20.32 SV1.EE 4.45,20.32 3.17,20.32 SV1.CC 1.91,20.32 0.64,20.32 SV1.AA -0.64,20.32 -1.91,20.32 SV1.Y -3.17,20.32 -4.45,20.32 SV1.W -5.71,20.32 -6.99,20.32 SV1.U -8.26,20.32 -9.53,20.32 SV1.S -10.79,20.32 -12.06,20.32 SV1.P -13.34,20.32 -14.61,20.32 SV1.M -15.88,20.32 -17.14,20.32 SV1.K -18.41,20.32 -19.68,20.32 SV1.H -20.95,20.32 -22.23,20.32 SV1.E -23.5,20.32 -24.77,20.32 SV1.C -26.04,20.32 -27.3,20.32 SV1.A -27.94,20.95 -27.94,22.23 SV1.B | 46.99,50.8 48.26,52.07 IC10.7 | 46.99,50.8 46.99,17.78 48.26,16.51 IC9.7 | 46.99,50.8 46.99,62.23 48.26,63.5 48.26,109.22 IC11.7 | SV4.C -26.04,137.16 -27.3,137.16 SV4.A -27.94,137.79 -27.94,139.06 SV4.B | SV4.E -23.5,137.16 -24.77,137.16 SV4.C | SV4.D -25.4,139.06 -25.4,137.79 SV4.C | SV4.F -22.86,139.06 -22.86,137.79 SV4.E | SV4.H -20.95,137.16 -22.23,137.16 SV4.E | SV4.J -20.32,139.06 -20.32,137.79 SV4.H | SV4.H -19.68,137.16 -18.41,137.16 SV4.K -17.14,137.16 -15.88,137.16 SV4.M | SV4.N -15.24,139.06 -15.24,137.79 SV4.M | SV4.P -13.34,137.16 -14.61,137.16 SV4.M | SV4.T -10.16,139.06 -10.16,137.79 SV4.S -9.53,137.16 -8.26,137.16 SV4.U -6.99,137.16 -5.71,137.16 SV4.W | SV4.X -5.08,139.06 -5.08,137.79 SV4.W
  Top 0.254: SV4.W -4.45,137.16 -3.17,137.16 SV4.Y -1.91,137.16 -0.64,137.16 SV4.AA | SV4.BB 0,139.06 0,137.79 SV4.AA | SV4.AA 0.64,137.16 1.91,137.16 SV4.CC 3.17,137.16 4.45,137.16 SV4.EE 5.08,137.79 5.08,139.06 SV4.FF | SV4.KK 9.53,137.16 8.26,137.16 SV4.HH | SV4.LL 10.16,139.06 10.16,137.79 SV4.KK | SV4.KK 10.79,137.16 12.06,137.16 SV4.MM 13.34,137.16 14.61,137.16 SV4.PP | SV4.RR 15.24,139.06 15.24,137.79 SV4.PP | SV4.SS 17.14,137.16 15.88,137.16 SV4.PP | SV9.C -26.04,152.4 -27.3,152.4 SV9.A -27.94,153.03 -27.94,154.31 SV9.B | SV9.E -23.5,152.4 -24.77,152.4 SV9.C | SV9.E -22.23,152.4 -20.95,152.4 SV9.H -20.32,153.03 -20.32,154.31 SV9.J | SV9.D -25.4,154.31 -25.4,153.03 SV9.C | SV9.F -22.86,154.31 -22.86,153.03 SV9.E | SV9.M -15.88,152.4 -17.14,152.4 SV9.K | SV9.P -13.34,152.4 -14.61,152.4 SV9.M | SV9.N -15.24,154.31 -15.24,153.03 SV9.M | SV9.T -10.16,154.31 -10.16,153.03 SV9.S | SV9.U -6.99,152.4 -5.71,152.4 SV9.W -5.08,153.03 -5.08,154.31 SV9.X | SV9.Y -1.91,152.4 -0.64,152.4 SV9.AA 0,153.03 0,154.31 SV9.BB | SV9.CC 3.17,152.4 4.45,152.4 SV9.EE 5.08,153.03 5.08,154.31 SV9.FF | SV9.LL 10.16,154.31 10.16,153.03 SV9.KK 10.79,152.4 12.06,152.4 SV9.MM | SV9.RR 15.24,154.31 15.24,153.03 SV9.PP 15.88,152.4 17.14,152.4 SV9.SS 18.41,152.4 19.68,152.4 SV9.UU | SV9.UU 20.32,153.03 20.32,154.31 SV9.VV 20.32,155.57 20.32,173.35 SV5.UU | SV3.B -27.94,100.97 -27.94,99.69 SV3.A -27.3,99.06 -26.04,99.06 SV3.C -24.77,99.06 -23.5,99.06 SV3.E -22.23,99.06 -20.95,99.06 SV3.H -19.68,99.06 -18.41,99.06 SV3.K -17.14,99.06 -15.88,99.06 SV3.M | SV3.P -12.06,99.06 -10.79,99.06 SV3.S -9.53,99.06 -8.26,99.06 SV3.U -6.99,99.06 -5.71,99.06 SV3.W -4.45,99.06 -3.17,99.06 SV3.Y -1.91,99.06 -0.64,99.06 SV3.AA 0.64,99.06 1.91,99.06 SV3.CC 3.17,99.06 4.45,99.06 SV3.EE 5.71,99.06 6.99,99.06 SV3.HH 8.26,99.06 9.53,99.06 SV3.KK 10.79,99.06 12.06,99.06 SV3.MM
  Top 0.254: SV3.SS 17.14,99.06 15.88,99.06 SV3.PP | SV8.C -24.77,119.38 -23.5,119.38 SV8.E -22.23,119.38 -20.95,119.38 SV8.H | SV8.M -14.61,119.38 -13.34,119.38 SV8.P -12.06,119.38 -10.79,119.38 SV8.S -9.53,119.38 -8.26,119.38 SV8.U -6.99,119.38 -5.71,119.38 SV8.W -4.45,119.38 -3.17,119.38 SV8.Y -1.91,119.38 -0.64,119.38 SV8.AA 0.64,119.38 1.91,119.38 SV8.CC 3.17,119.38 4.45,119.38 SV8.EE 5.71,119.38 6.99,119.38 SV8.HH 8.26,119.38 9.53,119.38 SV8.KK 10.79,119.38 12.06,119.38 SV8.MM | SV8.B -27.94,121.28 -27.94,120.02 SV8.A | 46.99,250.19 46.99,259.08 48.26,260.35 IC13.7 | 46.99,250.19 46.99,189.23 48.26,187.96 IC12.7 | M916_19.C2 -36.83,224.79 -37.47,225.43 -37.47,236.22 -36.83,236.85 M916_20.C2 | SV5.H -20.95,173.99 -22.23,173.99 SV5.E -23.5,173.99 -24.77,173.99 SV5.C -26.04,173.99 -27.3,173.99 SV5.A -27.94,174.62 -27.94,175.9 SV5.B -27.94,177.16 -27.94,189.87 SV10.A -27.94,191.13 -27.94,192.41 SV10.B | SV10.C -24.77,190.5 -23.5,190.5 SV10.E -22.23,190.5 -20.95,190.5 SV10.H | SV10.K -17.14,190.5 -15.88,190.5 SV10.M -14.61,190.5 -13.34,190.5 SV10.P -12.06,190.5 -10.79,190.5 SV10.S -9.53,190.5 -8.26,190.5 SV10.U | SV10.W -5.71,190.5 -6.99,190.5 SV10.U | SV10.Y -1.91,190.5 -0.64,190.5 SV10.AA 0.64,190.5 1.27,190.5 | 1.27,190.5 1.91,190.5 SV10.CC 3.17,190.5 4.45,190.5 SV10.EE 5.71,190.5 6.99,190.5 SV10.HH 8.26,190.5 9.53,190.5 SV10.KK 10.79,190.5 12.06,190.5 SV10.MM | SV10.V -7.62,192.41 -7.62,191.13 SV10.U | SV5.K -17.14,173.99 -15.88,173.99 SV5.M -14.61,173.99 -13.34,173.99 SV5.P -12.06,173.99 -10.79,173.99 SV5.S -9.53,173.99 -8.26,173.99 SV5.U -7.62,174.62 -7.62,175.9 SV5.V
  Top 0.254: SV5.Y -1.91,173.99 -0.64,173.99 SV5.AA 0.64,173.99 1.91,173.99 SV5.CC 3.17,173.99 4.45,173.99 SV5.EE 5.71,173.99 6.99,173.99 SV5.HH 8.26,173.99 9.53,173.99 SV5.KK 10.79,173.99 12.06,173.99 SV5.MM 13.34,173.99 14.61,173.99 SV5.PP 15.88,173.99 17.14,173.99 SV5.SS 18.41,173.99 19.68,173.99 SV5.UU | SV5.UU 20.32,174.62 20.32,175.9 SV5.VV 20.32,177.16 20.32,189.87 SV10.UU 20.32,191.13 20.32,192.41 SV10.VV | SV10.MM 12.7,191.13 13.97,192.41 13.97,248.92 IC1.12 13.97,251.46 13.97,255.27 v13.34,255.91 | SV10.MM 13.34,190.5 14.61,190.5 SV10.PP 15.88,190.5 17.14,190.5 SV10.SS | v45.72,250.19 46.99,250.19 | 162.56,317.5 162.56,284.48 163.83,283.21 IC27.4 163.83,280.67 162.56,279.4 162.56,247.65 163.83,246.38 163.83,245.11 IC26.4 163.83,242.57 162.56,241.3 162.56,208.28 163.83,207.01 IC25.4 163.83,204.47 163.83,203.84 165.1,202.56 165.1,170.18 163.83,168.91 IC24.4 | 162.56,317.5 163.83,318.77 IC28.4 | 162.56,317.5 162.56,355.6 163.83,356.87 IC29.4 163.83,359.41 165.1,360.68 165.1,367.03 v160.02,372.11 | 86.36,87.63 86.36,60.96 85.09,59.69 M916_5.C2 | 86.36,87.63 86.36,88.9 87.63,90.17 IC17.7 | 86.36,87.63 83.82,90.17 v83.82,109.86 83.82,135.25 M916_6.C2 83.82,135.89 83.19,136.53 83.19,210.82 83.82,211.46 M916_7.C2 83.82,212.09 83.82,217.81 M916_7.C1 | M916_1.T1 126.36,227.33 127.64,226.06 127.64,220.98 128.27,220.34 128.27,218.44 M916_7.U1 | M916_7.T2 125.09,208.91 125.09,214.63 M916_7.T1 | IC19.7 88.9,260.35 88.9,246.38 87.63,245.11 IC18.7 87.63,242.57 85.72,240.66 85.72,225.43 85.09,224.79 M916_1.C2 | IC42.4 204.47,435.61 205.74,436.88 205.74,443.23 204.47,444.5 204.47,471.17 IC43.4 204.47,473.71 203.2,474.98 203.2,507.37 204.47,508.63 204.47,509.27 IC44.4 204.47,511.81 205.74,513.08 205.74,547.37 IC45.6
  Top 0.254: IC30.7 167.64,397.51 168.91,398.78 168.91,461.64 167.64,462.92 167.64,471.17 IC31.7 | IC55.5 242.57,511.81 241.3,513.08 241.3,534.67 240.03,535.94 IC56.11 240.03,538.48 241.3,539.75 241.3,572.77 240.03,574.04 IC57.11 | IC45.3 198.12,549.91 198.12,554.99 IC45.12 | IC45.7 207.65,548 206.38,548 IC45.6 | IC45.9 205.74,554.99 205.74,549.91 IC45.6 | IC33.4 163.83,585.47 168.28,581.02 168.28,558.16 168.91,557.53 168.91,551.18 167.64,549.91 IC32.7 | IC40.4 204.47,359.41 205.74,360.68 205.74,393.7 204.47,394.97 IC41.4 | M916_13.C2 284.48,573.4 284.48,553.72 288.29,549.91 IC69.7 288.29,547.37 286.38,545.47 286.38,498.48 285.75,497.84 M916_12.C2 285.75,497.2 285.75,474.98 289.56,471.17 IC68.7 289.56,468.63 287.02,466.09 287.02,436.88 | 287.02,436.88 288.29,435.61 IC67.7 | 287.02,436.88 287.02,398.78 288.29,397.51 IC66.7 288.29,394.97 288.29,368.3 287.02,367.03 287.02,355.6 | IC49.4 243.84,149.86 242.57,151.13 242.57,158.12 243.84,159.38 243.84,185.42 IC50.4 243.84,187.96 243.84,189.23 242.57,190.5 v242.57,205.1 242.57,222.25 | 242.57,222.25 243.84,223.52 IC51.4 | 242.57,222.25 242.57,233.68 243.84,234.95 243.84,261.62 IC52.4 | IC59.7 288.29,35.56 289.56,36.83 289.56,49.53 288.29,50.8 288.29,109.22 IC60.7 288.29,111.76 287.02,113.03 287.02,189.23 | 287.02,189.23 288.29,187.96 IC61.7 | 287.02,189.23 287.02,241.3 288.29,242.57 IC62.7 288.29,245.11 287.02,246.38 287.02,252.73 288.29,254 288.29,280.67 IC63.7 288.29,283.21 287.02,284.48 287.02,317.5 | 287.02,317.5 288.29,318.77 IC64.7 | 287.02,355.6 288.29,356.87 IC65.7 | 287.02,355.6 287.02,317.5
  Top 0.254: v247.65,266.7 247.65,280.67 IC53.7 | 527.05,146.05 528.32,147.32 IC115.7 | 527.05,146.05 527.05,113.03 528.32,111.76 IC114.7 528.32,109.22 529.59,107.95 529.59,74.93 528.32,73.66 IC113.7 528.32,71.12 525.78,68.58 525.78,24.13 IC112.9 525.78,21.59 528.32,19.05 528.32,16.51 IC112.7 | 527.05,146.05 527.05,157.48 527.68,158.12 527.68,201.29 528.32,201.93 IC116.7 528.32,204.47 529.59,205.74 529.59,241.3 528.32,242.57 IC117.7 528.32,245.11 529.59,246.38 529.59,322.58 | IC126.11 600.71,43.18 599.44,44.45 599.44,74.93 600.71,76.2 600.71,78.74 IC127.11 600.71,81.28 600.71,85.72 599.44,87 599.44,111.76 600.08,112.39 600.08,116.2 600.71,116.84 IC128.11 | IC104.7 487.68,7.62 488.95,8.89 v488.95,17.78 488.95,41.91 487.68,43.18 IC105.7 | IC107.7 487.68,187.96 488.95,189.23 488.95,235.59 487.68,236.85 487.68,261.62 IC108.7 487.68,264.16 488.95,265.43 488.95,281.94 486.41,284.48 486.41,316.87 487.68,318.13 487.68,318.77 IC109.7 487.68,321.31 488.95,322.58 488.95,374.65 487.68,375.92 IC110.7 | 529.59,379.73 528.32,378.46 IC119.7 | 529.59,379.73 529.59,412.75 528.32,414.02 IC120.7 528.32,416.56 529.59,417.83 529.59,455.93 | 529.59,455.93 529.59,508 528.32,509.27 IC122.7 | 529.59,455.93 528.32,454.66 IC121.7 | 529.59,322.58 528.32,321.31 IC118.7 | 529.59,322.58 529.59,379.73 | IC129.7 608.33,160.02 607.06,161.29 607.06,194.31 608.33,195.58 IC130.7 608.33,198.12 607.06,199.39 607.06,205.74 608.33,207.01 608.33,233.68 IC131.7 608.33,236.22 607.7,236.85 607.7,240.66 607.06,241.3 607.06,260.35 | 607.06,260.35 608.33,261.62 IC132.7 | 607.06,279.4 608.33,280.67 IC133.7
  Top 0.254: 607.06,279.4 607.06,260.35 | 607.06,298.45 608.33,299.72 IC134.7 | 607.06,298.45 607.06,279.4 | 607.06,298.45 607.06,317.5 608.33,318.77 IC135.7 608.33,321.31 607.06,322.58 607.06,374.65 608.33,375.92 IC136.7 608.33,378.46 609.6,379.73 609.6,412.75 608.33,414.02 IC137.7 608.33,416.56 609.6,417.83 609.6,450.85 608.33,452.12 IC138.7 608.33,454.66 607.06,455.93 607.06,488.95 | IC141.7 608.33,566.42 609.6,565.15 609.6,532.13 608.33,530.86 IC140.7 608.33,528.32 607.06,527.05 607.06,488.95 | 607.06,488.95 608.33,490.22 IC139.7 | 408.94,69.85 408.94,-1.27 407.67,-2.54 IC83.7 | 408.94,69.85 407.67,71.12 IC84.7 | 408.94,69.85 408.94,146.05 407.67,147.32 IC85.7 407.67,149.86 406.4,151.13 406.4,227.33 | v447.04,142.24 447.04,132.08 448.31,130.81 IC93.7 | 326.39,69.85 325.75,69.22 325.75,60.33 325.12,59.69 M916_14.C2 325.12,59.05 326.39,57.78 326.39,36.83 327.66,35.56 IC71.7 327.66,33.02 328.93,31.75 328.93,-1.27 327.66,-2.54 IC70.7 | 326.39,69.85 327.66,71.12 IC72.7 | 326.39,69.85 326.39,109.22 327.66,110.49 IC73.7 327.66,113.03 323.85,116.84 323.85,135.25 M916_15.C2 323.85,135.89 323.21,136.53 323.21,165.74 323.85,166.37 323.85,168.91 326.39,171.45 | M916_16.T2 365.12,208.91 365.12,214.63 M916_16.T1 | 406.4,227.33 407.67,226.06 IC86.7 | 406.4,227.33 406.4,241.3 407.67,242.57 IC87.7 | 326.39,185.42 326.39,171.45 | 326.39,171.45 326.39,170.18 327.66,168.91 IC74.7 | 326.39,185.42 327.66,186.69 IC75.7 | 326.39,185.42 326.39,210.19 325.12,211.46 M916_16.C2 325.12,212.09 326.39,213.36 326.39,246.38 | 326.39,246.38 327.66,245.11 IC76.7 | 326.39,246.38 326.39,264.16 327.66,265.43 IC77.7 327.66,267.97 323.85,271.78 323.85,287.65 M916_17.C2 323.85,288.29 323.21,288.93 323.21,295.27 323.85,295.91 v323.85,319.4 323.85,353.06 327.66,356.87 IC78.7
  Top 0.254: IC81.7 368.3,454.66 369.57,455.93 v369.57,502.92 369.57,527.05 368.3,528.32 IC82.7 | IC91.7 407.67,490.22 406.4,488.95 406.4,474.98 407.67,473.71 IC90.7 407.67,471.17 406.4,469.9 v406.4,452.75 406.4,433.7 | 406.4,393.7 407.67,394.97 IC89.7 | 406.4,393.7 406.4,379.73 407.67,378.46 IC88.7 | 406.4,433.7 406.4,393.7 | 449.58,527.05 v449.58,511.81 449.58,494.03 448.31,492.76 IC101.7 448.31,490.22 449.58,488.95 449.58,457.83 448.31,456.56 448.31,454.66 IC100.7 448.31,452.12 447.04,450.85 447.04,438.15 448.31,436.88 448.31,435.61 IC99.7 448.31,433.07 447.04,431.8 447.04,408.94 448.31,407.67 IC98.7 448.31,405.13 447.04,403.86 447.04,365.76 | 449.58,527.05 448.31,528.32 IC102.7 | 449.58,527.05 449.58,575.31 448.31,576.58 IC103.7 | IC94.11 440.69,252.73 441.96,254 441.96,287.02 440.69,288.29 IC95.11 440.69,290.83 v440.69,302.26 440.69,321.31 447.04,327.66 | 447.04,327.66 448.31,328.93 IC96.7 | 447.04,365.76 448.31,367.03 IC97.7 | 447.04,327.66 447.04,365.76 | v408.31,433.7 406.4,433.7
